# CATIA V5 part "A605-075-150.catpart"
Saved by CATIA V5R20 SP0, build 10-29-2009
Part number: A605-075-150
Source: Unknown
Property "A": "45.000"
Property "ARTICLENO": "A605-075-150"
Property "BOMINFO": "A605-075-150"
Property "CODE": "A605-075-150"
Property "D": "9.000"
Property "FORM": "D"
Property "L": "150.000"
Property "L1": "60.000"
Property "LINA": "A605-075-150"
Property "NB": "A605-075-150"
Property "NBSYN": "$CODE."
Property "NN": "A605"
Property "NT": "Wear Plates, self-lubricating"
Property "SCREW": "6*M8X16"
Property "SUPPLIER": "CF"
Property "W": "75.000"
Bounding box of the stored display mesh (mm): x -75 to 0, y 0 to 5, z -150 to 0
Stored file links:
  C:\Users\Utente\Desktop\3D files A605\A605-075-150.catpart
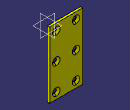
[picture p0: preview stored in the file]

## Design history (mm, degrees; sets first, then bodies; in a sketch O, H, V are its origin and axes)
Body1 "Geometry.1" (main body)
  Solid1 "A605-075-150.catpart": solid without history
